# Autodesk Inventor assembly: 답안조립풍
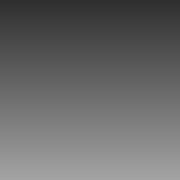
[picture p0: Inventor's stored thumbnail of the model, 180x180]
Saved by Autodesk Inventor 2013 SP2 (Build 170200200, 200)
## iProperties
Created: 2024-04
Part Number: 답안조립풍
Document SubType Name: Weldment
Designer: a
Weld Material: Welded Aluminum-6061
Author: a
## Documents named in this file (1)
- C:\Users\a\Downloads\740404V1006 (1)\답안조립풍.iam
